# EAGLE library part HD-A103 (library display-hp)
LED DISPLAY 1-character 7 segment, decimal point right
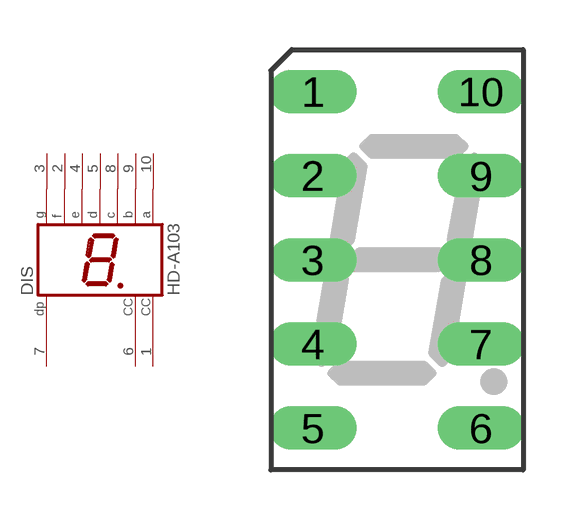
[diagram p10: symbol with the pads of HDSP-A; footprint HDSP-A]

Designator prefix DIS

## HD-A103 (OC_FARNELL: unknown; OC_NEWARK: unknown)  [HDSP-A]
1  CC  pas
2  F  pas
3  G  pas
4  E  pas
5  D  pas
6  CC  pas
7  DP  pas
8  C  pas
9  B  pas
10  A  pas

## Footprint HDSP-A (pad centres in mm)
LED DISPLAY 8-mm 1 character 7 segment, decimal point right
drill 0.813 long: 1 -2.54,5.08; 2 -2.54,2.54; 3 -2.54,0; 4 -2.54,-2.54; 5 -2.54,-5.08; 6 2.54,-5.08; 7 2.54,-2.54; 8 2.54,0; 9 2.54,2.54; 10 2.54,5.08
